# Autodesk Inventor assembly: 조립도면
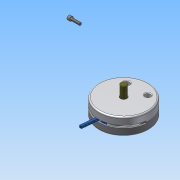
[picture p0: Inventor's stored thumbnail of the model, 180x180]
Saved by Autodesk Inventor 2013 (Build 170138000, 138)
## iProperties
Created: 2015-04
Part Number: 조립도면
Document SubType Name: Assembly
Designer: Administrator
Author: Administrator
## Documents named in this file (10)
- C:\Users\Administrator\Desktop\450406V1034\조립도면.iam
- C:\Users\Administrator\Desktop\450406V1034\본체.ipt
- C:\Users\Administrator\Desktop\450406V1034\M 10 x 35.ipt
- C:\Users\Administrator\Desktop\450406V1034\덮개.ipt
- C:\Users\Administrator\Desktop\450406V1034\멈춤링.ipt
- C:\Users\Administrator\Desktop\450406V1034\베어링62_22.ipt
- C:\Users\Administrator\Desktop\450406V1034\슬라이더.ipt
- C:\Users\Administrator\Desktop\450406V1034\슬라이더2.ipt
- C:\Users\Administrator\Desktop\450406V1034\축.ipt
- C:\Users\Administrator\Desktop\450406V1034\평행핀.ipt
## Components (1 placed, 1 different names)
1. M 10 x 35:1
